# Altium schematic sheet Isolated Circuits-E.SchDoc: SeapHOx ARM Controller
size Letter; Organization: Martz Lab, 858-534-0573; Address1: trmartz@ucsd.edu; Address2: Geosciences Research; Address3: Division, Scripps Institution; Address4: of Oceanography, UCSD; DocumentNumber: 1; Revision: E; SheetNumber: 1; SheetTotal: 7
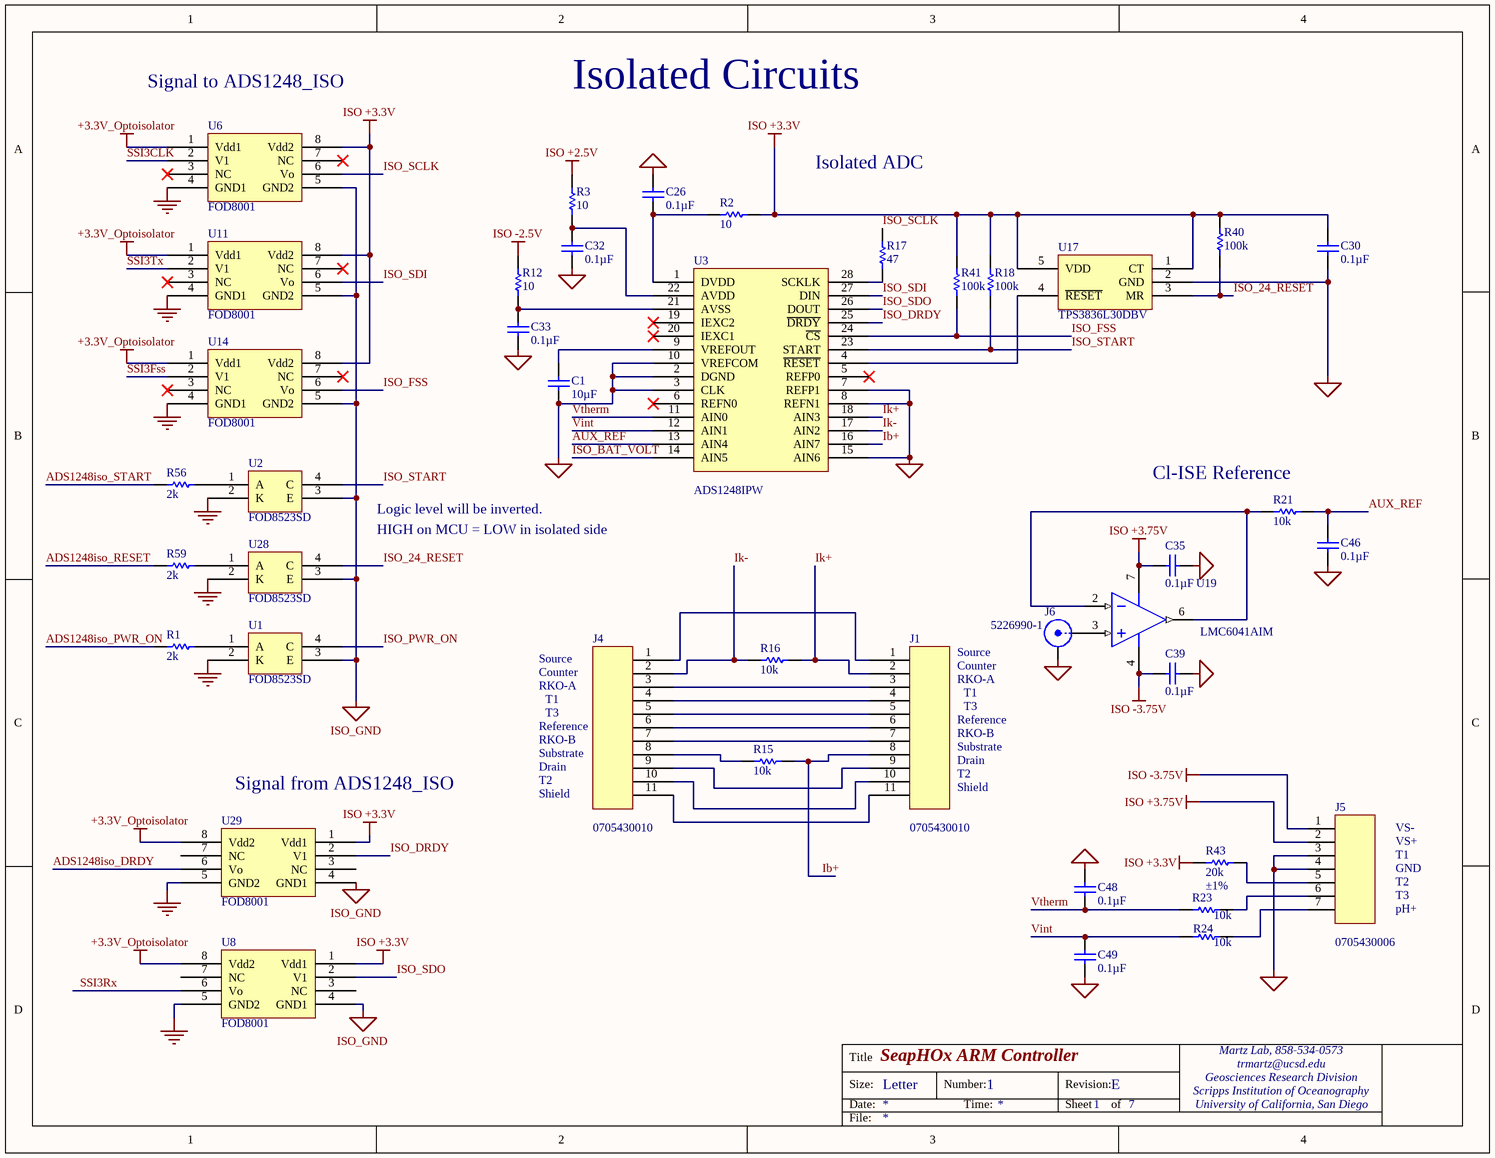
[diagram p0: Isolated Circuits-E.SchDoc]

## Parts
C1  Capacitance: 10µF  [CAPC0603(1608)100_M]  (hidden comment: C1608X5R1A106K080AC)
C26  Capacitance: 0.1µF  [CAPC0603(1608)100_M]  (hidden comment: 0.1uF/50V)
C30  Capacitance: 0.1µF  [CAPC0603(1608)100_M]  (hidden comment: 0.1uF/50V)
C32  Capacitance: 0.1µF  [CAPC0603(1608)100_M]  (hidden comment: 0.1uF/50V)
C33  Capacitance: 0.1µF  [CAPC0603(1608)100_M]  (hidden comment: 0.1uF/50V)
C35  Capacitance: 0.1µF  [CAPC0603(1608)100_M]  (hidden comment: 0.1uF/50V)
C39  Capacitance: 0.1µF  [CAPC0603(1608)100_M]  (hidden comment: 0.1uF/50V)
C46  Capacitance: 0.1µF  [CAPC0603(1608)100_M]  (hidden comment: 0.1uF/50V)
C48  Capacitance: 0.1µF  [CAPC0603(1608)100_M]  (hidden comment: 0.1uF/50V)
C49  Capacitance: 0.1µF  [CAPC0603(1608)100_M]  (hidden comment: 0.1uF/50V)
J1  0705430010  [70543-0010]
J4  0705430010  [70543-0010]
J5  0705430006  [70543-0006]
J6  5226990-1  [5226990-1]
R1  Resistance (Ohms): 2k  [RESC0805(2012)_N]  (hidden comment: ERJ-6GEYJ202V)
R2  Resistance (Ohms): 10  [RESC0805(2012)_N]  (hidden comment: ERJ-6GEYJ100V)
R3  Resistance (Ohms): 10  [RESC0805(2012)_N]  (hidden comment: ERJ-6GEYJ100V)
R12  Resistance (Ohms): 10  [RESC0805(2012)_N]  (hidden comment: ERJ-6GEYJ100V)
R15  Resistance (Ohms): 10k  [RESC0805(2012)_N]  (hidden comment: ERJ-6GEYJ103V)
R16  Resistance (Ohms): 10k  [RESC0805(2012)_N]  (hidden comment: ERJ-6GEYJ103V)
R17  Resistance (Ohms): 47  [RESC0603(1608)_N]  (hidden comment: ERJ-3GEYJ470V)
R18  Resistance (Ohms): 100k  [RESC0805(2012)_N]  (hidden comment: ERJ-6GEYJ104V)
R21  Resistance (Ohms): 10k  [RESC0805(2012)_N]  (hidden comment: ERJ-6GEYJ103V)
R23  Resistance (Ohms): 10k  [RESC0805(2012)_N]  (hidden comment: ERJ-6GEYJ103V)
R24  Resistance (Ohms): 10k  [RESC0805(2012)_N]  (hidden comment: ERJ-6GEYJ103V)
R40  Resistance (Ohms): 100k  [RESC0805(2012)_N]  (hidden comment: ERJ-6GEYJ104V)
R41  Resistance (Ohms): 100k  [RESC0805(2012)_N]  (hidden comment: ERJ-6GEYJ104V)
R43  Resistance (Ohms): 20k  Tolerance: ±1%  [RESC0805(2012)_N]  (hidden comment: ERJ-6ENF2002V)
R56  Resistance (Ohms): 2k  [RESC0805(2012)_N]  (hidden comment: ERJ-6GEYJ202V)
R59  Resistance (Ohms): 2k  [RESC0805(2012)_N]  (hidden comment: ERJ-6GEYJ202V)
U1  FOD8523SD  [4-SMD]
U2  FOD8523SD  [4-SMD]
U3  ADS1248  [TSSOP28]  (value not drawn)
U6  FOD8001  [MS-012-AA]
U8  FOD8001  [MS-012-AA]
U11  FOD8001  [MS-012-AA]
U14  FOD8001  [MS-012-AA]
U17  TPS3836L30DBV  [SOT23-5]
U19  LMC6041AIM  [MS-012-AA]
U28  FOD8523SD  [4-SMD]
U29  FOD8001  [MS-012-AA]

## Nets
+3.3V_Optoisolator: U6.1(Vdd1) U8.8(Vdd2) U11.1(Vdd1) U14.1(Vdd1) U29.8(Vdd2)
GND: U1.2(K) U2.2(K) U6.4(GND1) U8.5(GND2) U11.4(GND1) U14.4(GND1) U28.2(K) U29.5(GND2)
ISO +2.5V: R3.2
ISO +3.3V: C30.2 R2.2 R18.2 R40.2 R41.2 R43.1 U6.8(Vdd2) U8.1(Vdd1) U11.8(Vdd2) U14.8(Vdd2) U17.1(CT) U17.5(VDD) U29.1(Vdd1)
ISO +3.75V: C35.2 J5.2 U19.7(V+)
ISO -2.5V: R12.2
ISO -3.75V: C39.2 J5.1 U19.4(V-)
ISO_GND: C1.1 C26.2 C30.1 C32.1 C33.1 C35.1 C39.1 C46.1 C48.2 C49.1 J5.3 J5.4 J6.2(Y) U1.3(E) U2.3(E) U3.2(DGND) U3.3(CLK) U3.7(REFP1) U3.8(REFN1) U3.10(VREFCOM) U3.15(AIN6) U6.5(GND2) U8.4(GND1) U11.5(GND2) U14.5(GND2) U17.2(GND) U28.3(E) U29.4(GND1)
ADS1248iso_DRDY: U29.6(Vo)
ADS1248iso_PWR_ON: R1.1
ADS1248iso_RESET: R59.1
ADS1248iso_START: R56.1
AUX_REF: C46.2 R21.2 U3.13(AIN4)
Ib+: J1.8 R15.2 U3.16(AIN7)
Ik+: J1.2 R16.2 U3.18(AIN3)
Ik-: J4.2 R16.1 U3.17(AIN2)
ISO_24_RESET: R40.1 U17.3(MR) U28.4(C)
ISO_BAT_VOLT: U3.14(AIN5)
ISO_DRDY: U3.25(~{DRDY}) U29.2(V1)
ISO_FSS: R41.1 U3.24(~{CS}) U14.6(Vo)
ISO_PWR_ON: U1.4(C)
ISO_SCLK: R17.1 U6.6(Vo)
ISO_SDI: U3.27(DIN) U11.6(Vo)
ISO_SDO: U3.26(DOUT) U8.2(V1)
ISO_START: R18.1 U2.4(C) U3.23(START)
SSI3CLK: U6.2(V1)
SSI3Fss: U14.2(V1)
SSI3Rx: U8.6(Vo)
SSI3Tx: U11.2(V1)
Vint: C49.2 R24.1 U3.12(AIN1)
Vtherm: C48.1 R23.1 U3.11(AIN0)
NetC1_2: C1.2 U3.9(VREFOUT)
NetC26_1: C26.1 R2.1 U3.1(DVDD)
NetC32_2: C32.2 R3.1 U3.22(AVDD)
NetC33_2: C33.2 R12.1 U3.21(AVSS)
NetJ1_1: J1.1 J4.1
NetJ1_3: J1.3 J4.3
NetJ1_4: J1.4 J4.4
NetJ1_5: J1.5 J4.5
NetJ1_6: J1.6 J4.6
NetJ1_7: J1.7 J4.7
NetJ1_9: J1.9 J4.9
NetJ1_10: J1.10 J4.10
NetJ1_11: J1.11 J4.11
NetJ4_8: J4.8 R15.1
NetJ5_5: J5.5 R43.2
NetJ5_6: J5.6 R23.2
NetJ5_7: J5.7 R24.2
NetJ6_1: J6.1(X) U19.3(IN+)
NetR1_2: R1.2 U1.1(A)
NetR17_2: R17.2 U3.28(SCKLK)
NetR21_1: R21.1 U19.2(IN-) U19.6(OUT)
NetR56_2: R56.2 U2.1(A)
NetR59_2: R59.2 U28.1(A)
NetU3_4: U3.4(~{RESET}) U17.4(~{RESET})

Not connected (* = marked no-connect by the designer): U3 5(REFP0)* 6(REFN0)* 19(IEXC2)* 20(IEXC1)*; U6 3(NC)* 7(NC)*; U8 3(NC) 7(NC); U11 3(NC)* 7(NC)*; U14 3(NC)* 7(NC)*; U29 3(NC) 7(NC)

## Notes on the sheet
- Signal to ADS1248_ISO
- Isolated Circuits
- Isolated ADC
- (near R21) Cl-ISE Reference
- Logic level will be inverted.
- HIGH on MCU = LOW in isolated side
- Source
- (near J4) Counter
- RKO-A
- T1
- Counter
- (near J1) RKO-A
- (near J4) Reference
- RKO-B
- (near J4) Substrate
- Drain
- T3
- (near J1) Reference
- (near J1) RKO-B
- (near J1) Substrate
- (near J1) Drain
- (near J1) T2
- (near U29) Signal from ADS1248_ISO
- T2
- Shield
- (near J1) Shield
- VS-
- VS+
- GND
- pH+

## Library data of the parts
C1 = C1608X5R1A106K080AC: CAP CER 10UF 10V 10% X5R 0603; Manufacturer: TDK Corporation
C26 C30 C32 C33 C35 C39 C46 C48 C49 = C0603C104K5RACTU: CAP CER 0.1UF 50V 10% X7R 0603; Manufacturer: Kemet
J1 J4 = 0705430010: CONN HEADER 11POS .100 VERT GOLD; Manufacturer: Molex Inc; Connector Type: Header, Shrouded; Number of Positions: 11; Number of Positions Loaded: All; Pitch: 0.100" (2.54mm)
J5 = 0705430006: CONN HEADER 7POS .100 VERT GOLD; Manufacturer: Molex Inc; Connector Type: Header, Shrouded; Number of Positions: 7; Number of Positions Loaded: All; Pitch: 0.100" (2.54mm)
J6 = 5226990-1: CONN BNC JACK R/A 50 OHM PCB; Manufacturer: TE Connectivity; Connector Type: Jack, Female Socket; Contact Termination: Solder; Impedance: 50 Ohm; Frequency - Max: 4GHz; Body Material: Zinc; Body Finish: Nickel; Center Contact Material: Phosphor Bronze; Center Contact Plating: Tin; Dielectric Material: Polymethylpentene (PMP)
R1 R56 R59 = ERJ-6GEYJ202V: RES 2K OHM 1/8W 5% 0805 SMD; Manufacturer: Panasonic Electronic Components; Power (Watts): 0.125W, 1/8W; Temperature Coefficient: ±200ppm/°C
R2 R3 R12 = ERJ-6GEYJ100V: RES 10 OHM 1/8W 5% 0805 SMD; Manufacturer: Panasonic Electronic Components; Power (Watts): 0.125W, 1/8W; Temperature Coefficient: ±200ppm/°C
R15 R16 R21 R23 R24 = ERJ-6GEYJ103V: RES 10K OHM 1/8W 5% 0805 SMD; Manufacturer: Panasonic Electronic Components; Power (Watts): 0.125W, 1/8W; Temperature Coefficient: ±200ppm/°C
R17 = ERJ-3GEYJ470V: RES 47 OHM 1/10W 5% 0603 SMD; Manufacturer: Panasonic Electronic Components; Power (Watts): 0.1W, 1/10W; Temperature Coefficient: ±200ppm/°C
R18 R40 R41 = ERJ-6GEYJ104V: RES 100K OHM 1/8W 5% 0805 SMD; Manufacturer: Panasonic Electronic Components; Power (Watts): 0.125W, 1/8W; Temperature Coefficient: ±200ppm/°C
R43 = ERJ-6ENF2002V: RES 20K OHM 1/8W 1% 0805 SMD; Manufacturer: Panasonic Electronic Components; Power (Watts): 0.125W, 1/8W; Temperature Coefficient: ±100ppm/°C
U1 U2 U28 = FOD8523SD: OPTOCOUPLER DARL 5KVRMS 4SMD; Manufacturer: Fairchild Semiconductor; Number of Channels: 1; Input Type: DC; Voltage - Isolation: 5000Vrms; Current Transfer Ratio (Min): 1000% @ 1mA; Current Transfer Ratio (Max): 15000% @ 1mA; Voltage - Output: 300V; Current - Output / Channel: 150mA; Current - DC Forward (If): 50mA; Vce Saturation (Max): 1.2V; Output Type: Darlington
U3 = ADS1248IPW: IC ADC 24BIT DEL/SIG LN 28TSSOP; Manufacturer: Texas Instruments; Number of Bits: 24; Sampling Rate (Per Second): 2k; Data Interface: Serial, SPI™; Number of Converters: 1; Voltage Supply Source: Analog and Digital, Dual ±; Number of Inputs and Type: 7 Single-Ended, Unipolar; 7 Single-Ended, Bipolar; 4 Differential, Unipolar; 4 Differential, Bipolar
U6 U11 U14 = FOD8001: OPTOCOUPLER 3.3V 8-SOIC; Manufacturer: Fairchild Semiconductor; Voltage - Isolation: 3750Vrms; Number of Channels: 1, Unidirectional; Current - Output / Channel: 10mA; Data Rate: 25Mbps; Propagation Delay High - Low @ If: 25ns; Input Type: Logic; Output Type: Push-Pull, Totem Pole
U8 U29 = FOD8001: OPTOCOUPLER 3.3V 8-SOIC; Manufacturer: Fairchild Semiconductor; Voltage - Isolation: 3750Vrms; Number of Channels: 1, Unidirectional; Current - Output / Channel: 10mA; Input Type: Logic; Output Type: Push-Pull, Totem Pole; Data Rate: 25Mbps; Propagation Delay High - Low @ If: 25ns
U17 = TPS3836L30DBVT: IC 2.64V NANOPWR MON SOT-23-5; Manufacturer: Texas Instruments; Number of Voltages Monitored: 1; Output: Push-Pull, Totem Pole; Reset: Active Low; Reset Timeout: 100 ms Minimum
U19 = LMC6041AIM: IC OPAMP GP 75KHZ RRO 8SOIC; Manufacturer: Texas Instruments; Manufacturer Part Number: LMC6041AIM/NOPB; Amplifier Type: General Purpose; Number of Circuits: 1; Output Type: Rail-to-Rail; Slew Rate: 0.02 V/µs; Current - Input Bias: 0.002pA; Voltage - Input Offset: 1mV; Current - Supply: 18µA; Current - Output / Channel: 40mA; Voltage - Supply, Single/Dual (±): 4.5 V ~ 15.5 V, ±2.25 V ~ 7.75 V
